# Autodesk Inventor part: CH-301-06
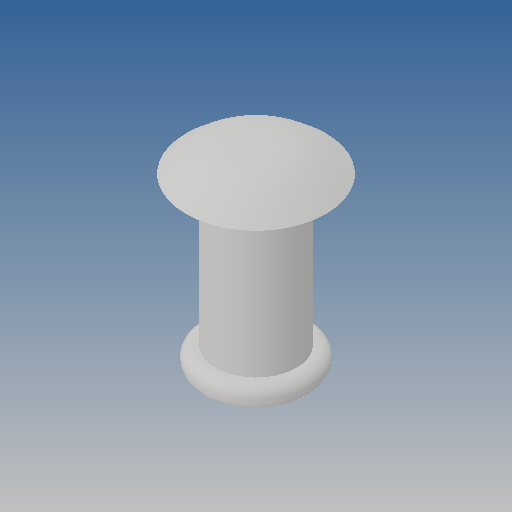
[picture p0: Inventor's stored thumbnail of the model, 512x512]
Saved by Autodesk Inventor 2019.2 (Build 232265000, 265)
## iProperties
Created: 2012-09
Part Number: CH-301-06
Material: Ogólny
Document SubType Name: Modeling
Designer: CADENGINEERING4
Density: 1 g/cm^3
Appearance: Domyślna
Author: CADENGINEERING4
Revision Number: ÈÎºÎ
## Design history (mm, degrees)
feature "Ô²½Ç4"
node "Bryła1"
